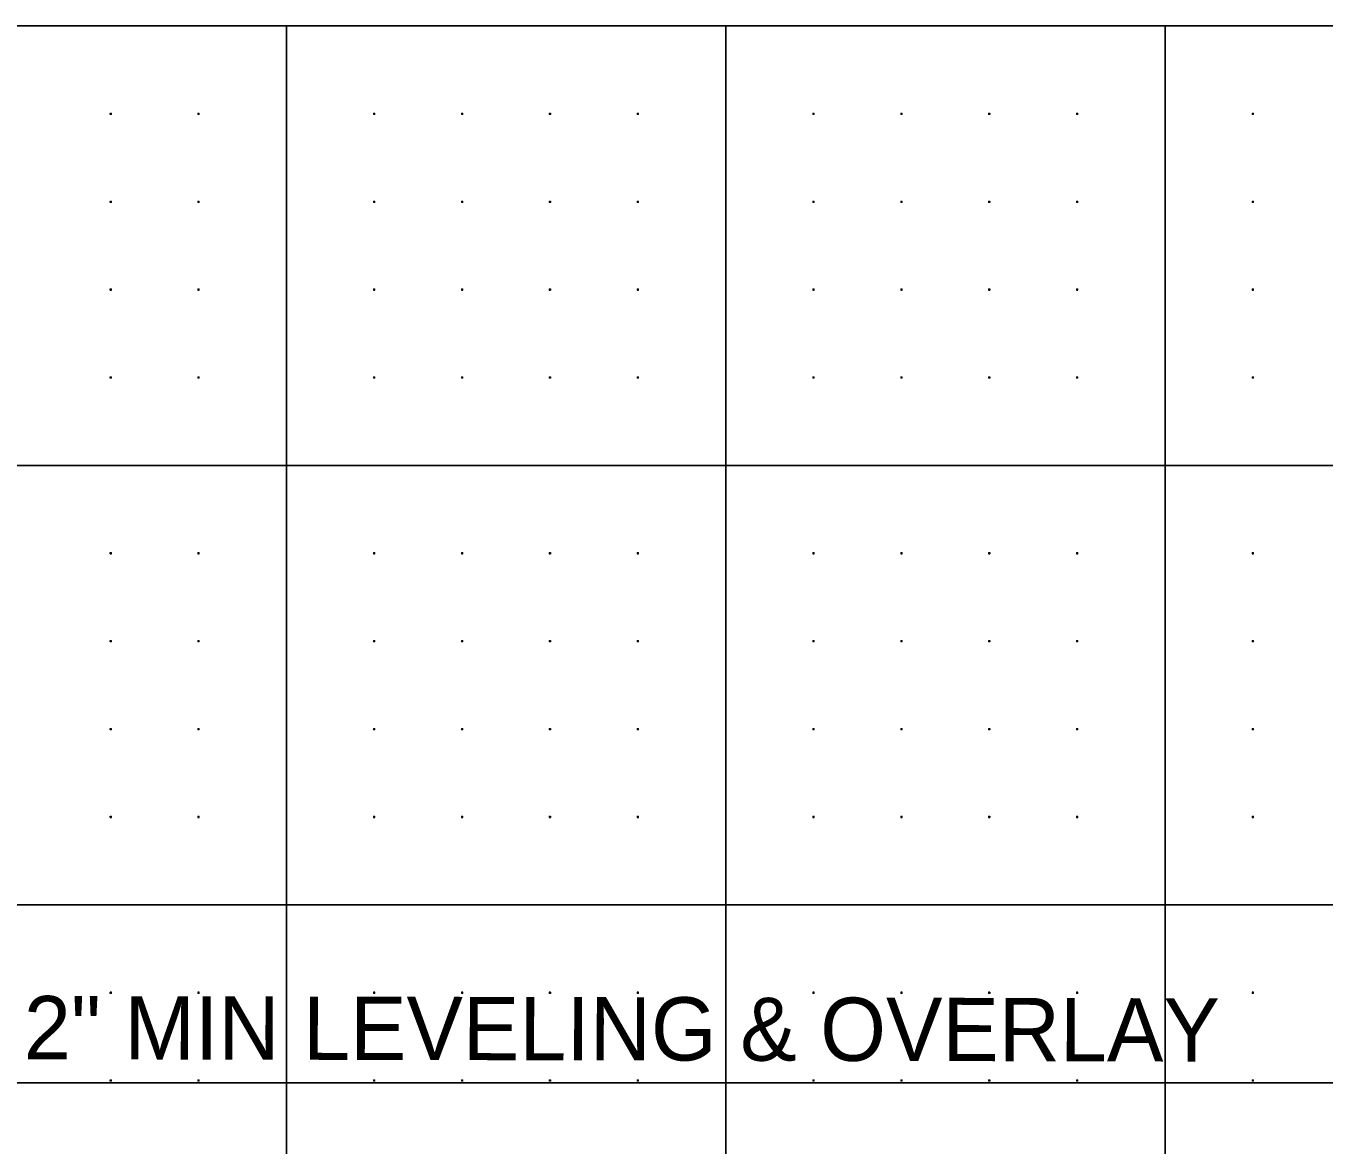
# Model space of a CAD drawing. Extents: x 471 to 2121, y 140 to 650.
# Drawn here: x 1206.4 to 1354.2, y 522.7 to 650 of the extents above; entities that cross this region are included whole.
import ezdxf

# ---------------------------------------------------------------- set-up
doc = ezdxf.new("R2010")
doc.units = 0
doc.layers.add('DSN_DRFT_Border Grid', color=7, linetype='Continuous')
doc.layers.add('Transition Dimensions', color=7, linetype='Continuous')

msp = doc.modelspace()

# ---------------------------------------------------------------- linework, layer by layer
at = {"layer": 'DSN_DRFT_Border Grid'}
for p, q in [((521.06, 650), (2071.06, 650)), ((521.06, 650), (2071.06, 650)), ((1236.06, 150), (1236.06, 650)), ((1236.06, 150), (1236.06, 650)), ((1286.06, 150), (1286.06, 650)), ((1286.06, 150), (1286.06, 650)), ((1336.06, 150), (1336.06, 650)), ((1336.06, 150), (1336.06, 650)), ((1216.18, 640), (1215.94, 640)), ((1216.18, 640), (1215.94, 640)), ((1216.06, 640.12), (1216.06, 639.88)), ((1216.06, 640.12), (1216.06, 639.88)), ((1226.18, 640), (1225.94, 640)), ((1226.18, 640), (1225.94, 640)), ((1226.06, 640.12), (1226.06, 639.88)), ((1226.06, 640.12), (1226.06, 639.88)), ((1246.18, 640), (1245.94, 640)), ((1246.18, 640), (1245.94, 640)), ((1246.06, 640.12), (1246.06, 639.88)), ((1246.06, 640.12), (1246.06, 639.88)), ((1256.18, 640), (1255.94, 640)), ((1256.18, 640), (1255.94, 640)), ((1256.06, 640.12), (1256.06, 639.88)), ((1256.06, 640.12), (1256.06, 639.88)), ((1266.18, 640), (1265.94, 640)), ((1266.18, 640), (1265.94, 640)), ((1266.06, 640.12), (1266.06, 639.88)), ((1266.06, 640.12), (1266.06, 639.88)), ((1276.18, 640), (1275.94, 640)), ((1276.18, 640), (1275.94, 640)), ((1276.06, 640.12), (1276.06, 639.88)), ((1276.06, 640.12), (1276.06, 639.88)), ((1296.18, 640), (1295.94, 640)), ((1296.18, 640), (1295.94, 640)), ((1296.06, 640.12), (1296.06, 639.88)), ((1296.06, 640.12), (1296.06, 639.88)), ((1306.18, 640), (1305.94, 640)), ((1306.18, 640), (1305.94, 640)), ((1306.06, 640.12), (1306.06, 639.88)), ((1306.06, 640.12), (1306.06, 639.88)), ((1316.18, 640), (1315.94, 640)), ((1316.18, 640), (1315.94, 640)), ((1316.06, 640.12), (1316.06, 639.88)), ((1316.06, 640.12), (1316.06, 639.88)), ((1326.18, 640), (1325.94, 640)), ((1326.18, 640), (1325.94, 640)), ((1326.06, 640.12), (1326.06, 639.88)), ((1326.06, 640.12), (1326.06, 639.88)), ((1346.18, 640), (1345.94, 640)), ((1346.18, 640), (1345.94, 640)), ((1346.06, 640.12), (1346.06, 639.88)), ((1346.06, 640.12), (1346.06, 639.88)), ((1216.18, 630), (1215.94, 630)), ((1216.18, 630), (1215.94, 630)), ((1216.06, 630.12), (1216.06, 629.88)), ((1216.06, 630.12), (1216.06, 629.88)), ((1226.18, 630), (1225.94, 630)), ((1226.18, 630), (1225.94, 630)), ((1226.06, 630.12), (1226.06, 629.88)), ((1226.06, 630.12), (1226.06, 629.88)), ((1246.18, 630), (1245.94, 630)), ((1246.18, 630), (1245.94, 630)), ((1246.06, 630.12), (1246.06, 629.88)), ((1246.06, 630.12), (1246.06, 629.88)), ((1256.18, 630), (1255.94, 630)), ((1256.18, 630), (1255.94, 630)), ((1256.06, 630.12), (1256.06, 629.88)), ((1256.06, 630.12), (1256.06, 629.88)), ((1266.18, 630), (1265.94, 630)), ((1266.18, 630), (1265.94, 630)), ((1266.06, 630.12), (1266.06, 629.88)), ((1266.06, 630.12), (1266.06, 629.88)), ((1276.18, 630), (1275.94, 630)), ((1276.18, 630), (1275.94, 630)), ((1276.06, 630.12), (1276.06, 629.88)), ((1276.06, 630.12), (1276.06, 629.88)), ((1296.18, 630), (1295.94, 630)), ((1296.18, 630), (1295.94, 630)), ((1296.06, 630.12), (1296.06, 629.88)), ((1296.06, 630.12), (1296.06, 629.88)), ((1306.18, 630), (1305.94, 630)), ((1306.18, 630), (1305.94, 630)), ((1306.06, 630.12), (1306.06, 629.88)), ((1306.06, 630.12), (1306.06, 629.88)), ((1316.18, 630), (1315.94, 630)), ((1316.18, 630), (1315.94, 630)), ((1316.06, 630.12), (1316.06, 629.88)), ((1316.06, 630.12), (1316.06, 629.88)), ((1326.18, 630), (1325.94, 630)), ((1326.18, 630), (1325.94, 630)), ((1326.06, 630.12), (1326.06, 629.88)), ((1326.06, 630.12), (1326.06, 629.88)), ((1346.18, 630), (1345.94, 630)), ((1346.18, 630), (1345.94, 630)), ((1346.06, 630.12), (1346.06, 629.88)), ((1346.06, 630.12), (1346.06, 629.88)), ((1216.18, 620), (1215.94, 620)), ((1216.18, 620), (1215.94, 620)), ((1216.06, 620.12), (1216.06, 619.88)), ((1216.06, 620.12), (1216.06, 619.88)), ((1226.18, 620), (1225.94, 620)), ((1226.18, 620), (1225.94, 620)), ((1226.06, 620.12), (1226.06, 619.88)), ((1226.06, 620.12), (1226.06, 619.88)), ((1246.18, 620), (1245.94, 620)), ((1246.18, 620), (1245.94, 620)), ((1246.06, 620.12), (1246.06, 619.88)), ((1246.06, 620.12), (1246.06, 619.88)), ((1256.18, 620), (1255.94, 620)), ((1256.18, 620), (1255.94, 620)), ((1256.06, 620.12), (1256.06, 619.88)), ((1256.06, 620.12), (1256.06, 619.88)), ((1266.18, 620), (1265.94, 620)), ((1266.18, 620), (1265.94, 620)), ((1266.06, 620.12), (1266.06, 619.88)), ((1266.06, 620.12), (1266.06, 619.88)), ((1276.18, 620), (1275.94, 620)), ((1276.18, 620), (1275.94, 620)), ((1276.06, 620.12), (1276.06, 619.88)), ((1276.06, 620.12), (1276.06, 619.88)), ((1296.18, 620), (1295.94, 620)), ((1296.18, 620), (1295.94, 620)), ((1296.06, 620.12), (1296.06, 619.88)), ((1296.06, 620.12), (1296.06, 619.88)), ((1306.18, 620), (1305.94, 620)), ((1306.18, 620), (1305.94, 620)), ((1306.06, 620.12), (1306.06, 619.88)), ((1306.06, 620.12), (1306.06, 619.88)), ((1316.18, 620), (1315.94, 620)), ((1316.18, 620), (1315.94, 620)), ((1316.06, 620.12), (1316.06, 619.88)), ((1316.06, 620.12), (1316.06, 619.88)), ((1326.18, 620), (1325.94, 620)), ((1326.18, 620), (1325.94, 620)), ((1326.06, 620.12), (1326.06, 619.88)), ((1326.06, 620.12), (1326.06, 619.88)), ((1346.18, 620), (1345.94, 620)), ((1346.18, 620), (1345.94, 620)), ((1346.06, 620.12), (1346.06, 619.88)), ((1346.06, 620.12), (1346.06, 619.88)), ((1216.18, 610), (1215.94, 610)), ((1216.18, 610), (1215.94, 610)), ((1216.06, 610.12), (1216.06, 609.88)), ((1216.06, 610.12), (1216.06, 609.88)), ((1226.18, 610), (1225.94, 610)), ((1226.18, 610), (1225.94, 610)), ((1226.06, 610.12), (1226.06, 609.88)), ((1226.06, 610.12), (1226.06, 609.88)), ((1246.18, 610), (1245.94, 610)), ((1246.18, 610), (1245.94, 610)), ((1246.06, 610.12), (1246.06, 609.88)), ((1246.06, 610.12), (1246.06, 609.88)), ((1256.18, 610), (1255.94, 610)), ((1256.18, 610), (1255.94, 610)), ((1256.06, 610.12), (1256.06, 609.88)), ((1256.06, 610.12), (1256.06, 609.88)), ((1266.18, 610), (1265.94, 610)), ((1266.18, 610), (1265.94, 610)), ((1266.06, 610.12), (1266.06, 609.88)), ((1266.06, 610.12), (1266.06, 609.88)), ((1276.18, 610), (1275.94, 610)), ((1276.18, 610), (1275.94, 610)), ((1276.06, 610.12), (1276.06, 609.88)), ((1276.06, 610.12), (1276.06, 609.88)), ((1296.18, 610), (1295.94, 610)), ((1296.18, 610), (1295.94, 610)), ((1296.06, 610.12), (1296.06, 609.88)), ((1296.06, 610.12), (1296.06, 609.88)), ((1306.18, 610), (1305.94, 610)), ((1306.18, 610), (1305.94, 610)), ((1306.06, 610.12), (1306.06, 609.88)), ((1306.06, 610.12), (1306.06, 609.88)), ((1316.18, 610), (1315.94, 610)), ((1316.18, 610), (1315.94, 610)), ((1316.06, 610.12), (1316.06, 609.88)), ((1316.06, 610.12), (1316.06, 609.88)), ((1326.18, 610), (1325.94, 610)), ((1326.18, 610), (1325.94, 610)), ((1326.06, 610.12), (1326.06, 609.88)), ((1326.06, 610.12), (1326.06, 609.88)), ((1346.18, 610), (1345.94, 610)), ((1346.18, 610), (1345.94, 610)), ((1346.06, 610.12), (1346.06, 609.88)), ((1346.06, 610.12), (1346.06, 609.88)), ((521.06, 600), (2071.06, 600)), ((521.06, 600), (2071.06, 600)), ((1216.18, 590), (1215.94, 590)), ((1216.18, 590), (1215.94, 590)), ((1216.06, 590.12), (1216.06, 589.88)), ((1216.06, 590.12), (1216.06, 589.88)), ((1226.18, 590), (1225.94, 590)), ((1226.18, 590), (1225.94, 590)), ((1226.06, 590.12), (1226.06, 589.88)), ((1226.06, 590.12), (1226.06, 589.88)), ((1246.18, 590), (1245.94, 590)), ((1246.18, 590), (1245.94, 590)), ((1246.06, 590.12), (1246.06, 589.88)), ((1246.06, 590.12), (1246.06, 589.88)), ((1256.18, 590), (1255.94, 590)), ((1256.18, 590), (1255.94, 590)), ((1256.06, 590.12), (1256.06, 589.88)), ((1256.06, 590.12), (1256.06, 589.88)), ((1266.18, 590), (1265.94, 590)), ((1266.18, 590), (1265.94, 590)), ((1266.06, 590.12), (1266.06, 589.88)), ((1266.06, 590.12), (1266.06, 589.88)), ((1276.18, 590), (1275.94, 590)), ((1276.18, 590), (1275.94, 590)), ((1276.06, 590.12), (1276.06, 589.88)), ((1276.06, 590.12), (1276.06, 589.88)), ((1296.18, 590), (1295.94, 590)), ((1296.18, 590), (1295.94, 590)), ((1296.06, 590.12), (1296.06, 589.88)), ((1296.06, 590.12), (1296.06, 589.88)), ((1306.18, 590), (1305.94, 590)), ((1306.18, 590), (1305.94, 590)), ((1306.06, 590.12), (1306.06, 589.88)), ((1306.06, 590.12), (1306.06, 589.88)), ((1316.18, 590), (1315.94, 590)), ((1316.18, 590), (1315.94, 590)), ((1316.06, 590.12), (1316.06, 589.88)), ((1316.06, 590.12), (1316.06, 589.88)), ((1326.18, 590), (1325.94, 590)), ((1326.18, 590), (1325.94, 590)), ((1326.06, 590.12), (1326.06, 589.88)), ((1326.06, 590.12), (1326.06, 589.88)), ((1346.18, 590), (1345.94, 590)), ((1346.18, 590), (1345.94, 590)), ((1346.06, 590.12), (1346.06, 589.88)), ((1346.06, 590.12), (1346.06, 589.88)), ((1216.18, 580), (1215.94, 580)), ((1216.18, 580), (1215.94, 580)), ((1216.06, 580.12), (1216.06, 579.88)), ((1216.06, 580.12), (1216.06, 579.88)), ((1226.18, 580), (1225.94, 580)), ((1226.18, 580), (1225.94, 580)), ((1226.06, 580.12), (1226.06, 579.88)), ((1226.06, 580.12), (1226.06, 579.88)), ((1246.18, 580), (1245.94, 580)), ((1246.18, 580), (1245.94, 580)), ((1246.06, 580.12), (1246.06, 579.88)), ((1246.06, 580.12), (1246.06, 579.88)), ((1256.18, 580), (1255.94, 580)), ((1256.18, 580), (1255.94, 580)), ((1256.06, 580.12), (1256.06, 579.88)), ((1256.06, 580.12), (1256.06, 579.88)), ((1266.18, 580), (1265.94, 580)), ((1266.18, 580), (1265.94, 580)), ((1266.06, 580.12), (1266.06, 579.88)), ((1266.06, 580.12), (1266.06, 579.88)), ((1276.18, 580), (1275.94, 580)), ((1276.18, 580), (1275.94, 580)), ((1276.06, 580.12), (1276.06, 579.88)), ((1276.06, 580.12), (1276.06, 579.88)), ((1296.18, 580), (1295.94, 580)), ((1296.18, 580), (1295.94, 580)), ((1296.06, 580.12), (1296.06, 579.88)), ((1296.06, 580.12), (1296.06, 579.88)), ((1306.18, 580), (1305.94, 580)), ((1306.18, 580), (1305.94, 580)), ((1306.06, 580.12), (1306.06, 579.88)), ((1306.06, 580.12), (1306.06, 579.88)), ((1316.18, 580), (1315.94, 580)), ((1316.18, 580), (1315.94, 580)), ((1316.06, 580.12), (1316.06, 579.88)), ((1316.06, 580.12), (1316.06, 579.88)), ((1326.18, 580), (1325.94, 580)), ((1326.18, 580), (1325.94, 580)), ((1326.06, 580.12), (1326.06, 579.88)), ((1326.06, 580.12), (1326.06, 579.88)), ((1346.18, 580), (1345.94, 580)), ((1346.18, 580), (1345.94, 580)), ((1346.06, 580.12), (1346.06, 579.88)), ((1346.06, 580.12), (1346.06, 579.88)), ((1216.18, 570), (1215.94, 570)), ((1216.18, 570), (1215.94, 570)), ((1216.06, 570.12), (1216.06, 569.88)), ((1216.06, 570.12), (1216.06, 569.88)), ((1226.18, 570), (1225.94, 570)), ((1226.18, 570), (1225.94, 570)), ((1226.06, 570.12), (1226.06, 569.88)), ((1226.06, 570.12), (1226.06, 569.88)), ((1246.18, 570), (1245.94, 570)), ((1246.18, 570), (1245.94, 570)), ((1246.06, 570.12), (1246.06, 569.88)), ((1246.06, 570.12), (1246.06, 569.88)), ((1256.18, 570), (1255.94, 570)), ((1256.18, 570), (1255.94, 570)), ((1256.06, 570.12), (1256.06, 569.88)), ((1256.06, 570.12), (1256.06, 569.88)), ((1266.18, 570), (1265.94, 570)), ((1266.18, 570), (1265.94, 570)), ((1266.06, 570.12), (1266.06, 569.88)), ((1266.06, 570.12), (1266.06, 569.88)), ((1276.18, 570), (1275.94, 570)), ((1276.18, 570), (1275.94, 570)), ((1276.06, 570.12), (1276.06, 569.88)), ((1276.06, 570.12), (1276.06, 569.88)), ((1296.18, 570), (1295.94, 570)), ((1296.18, 570), (1295.94, 570)), ((1296.06, 570.12), (1296.06, 569.88)), ((1296.06, 570.12), (1296.06, 569.88)), ((1306.18, 570), (1305.94, 570)), ((1306.18, 570), (1305.94, 570)), ((1306.06, 570.12), (1306.06, 569.88)), ((1306.06, 570.12), (1306.06, 569.88)), ((1316.18, 570), (1315.94, 570)), ((1316.18, 570), (1315.94, 570)), ((1316.06, 570.12), (1316.06, 569.88)), ((1316.06, 570.12), (1316.06, 569.88)), ((1326.18, 570), (1325.94, 570)), ((1326.18, 570), (1325.94, 570)), ((1326.06, 570.12), (1326.06, 569.88)), ((1326.06, 570.12), (1326.06, 569.88)), ((1346.18, 570), (1345.94, 570)), ((1346.18, 570), (1345.94, 570)), ((1346.06, 570.12), (1346.06, 569.88)), ((1346.06, 570.12), (1346.06, 569.88)), ((1216.18, 560), (1215.94, 560)), ((1216.18, 560), (1215.94, 560)), ((1216.06, 560.12), (1216.06, 559.88)), ((1216.06, 560.12), (1216.06, 559.88)), ((1226.18, 560), (1225.94, 560)), ((1226.18, 560), (1225.94, 560)), ((1226.06, 560.12), (1226.06, 559.88)), ((1226.06, 560.12), (1226.06, 559.88)), ((1246.18, 560), (1245.94, 560)), ((1246.18, 560), (1245.94, 560)), ((1246.06, 560.12), (1246.06, 559.88)), ((1246.06, 560.12), (1246.06, 559.88)), ((1256.18, 560), (1255.94, 560)), ((1256.18, 560), (1255.94, 560)), ((1256.06, 560.12), (1256.06, 559.88)), ((1256.06, 560.12), (1256.06, 559.88)), ((1266.18, 560), (1265.94, 560)), ((1266.18, 560), (1265.94, 560)), ((1266.06, 560.12), (1266.06, 559.88)), ((1266.06, 560.12), (1266.06, 559.88)), ((1276.18, 560), (1275.94, 560)), ((1276.18, 560), (1275.94, 560)), ((1276.06, 560.12), (1276.06, 559.88)), ((1276.06, 560.12), (1276.06, 559.88)), ((1296.18, 560), (1295.94, 560)), ((1296.18, 560), (1295.94, 560)), ((1296.06, 560.12), (1296.06, 559.88)), ((1296.06, 560.12), (1296.06, 559.88)), ((1306.18, 560), (1305.94, 560)), ((1306.18, 560), (1305.94, 560)), ((1306.06, 560.12), (1306.06, 559.88)), ((1306.06, 560.12), (1306.06, 559.88)), ((1316.18, 560), (1315.94, 560)), ((1316.18, 560), (1315.94, 560)), ((1316.06, 560.12), (1316.06, 559.88)), ((1316.06, 560.12), (1316.06, 559.88)), ((1326.18, 560), (1325.94, 560)), ((1326.18, 560), (1325.94, 560)), ((1326.06, 560.12), (1326.06, 559.88)), ((1326.06, 560.12), (1326.06, 559.88)), ((1346.18, 560), (1345.94, 560)), ((1346.18, 560), (1345.94, 560)), ((1346.06, 560.12), (1346.06, 559.88)), ((1346.06, 560.12), (1346.06, 559.88)), ((521.06, 550), (2071.06, 550)), ((521.06, 550), (2071.06, 550)), ((1216.18, 540), (1215.94, 540)), ((1216.18, 540), (1215.94, 540)), ((1216.06, 540.12), (1216.06, 539.88)), ((1216.06, 540.12), (1216.06, 539.88)), ((1226.18, 540), (1225.94, 540)), ((1226.18, 540), (1225.94, 540)), ((1226.06, 540.12), (1226.06, 539.88)), ((1226.06, 540.12), (1226.06, 539.88)), ((1246.18, 540), (1245.94, 540)), ((1246.18, 540), (1245.94, 540)), ((1246.06, 540.12), (1246.06, 539.88)), ((1246.06, 540.12), (1246.06, 539.88)), ((1256.18, 540), (1255.94, 540)), ((1256.18, 540), (1255.94, 540)), ((1256.06, 540.12), (1256.06, 539.88)), ((1256.06, 540.12), (1256.06, 539.88)), ((1266.18, 540), (1265.94, 540)), ((1266.18, 540), (1265.94, 540)), ((1266.06, 540.12), (1266.06, 539.88)), ((1266.06, 540.12), (1266.06, 539.88)), ((1276.18, 540), (1275.94, 540)), ((1276.18, 540), (1275.94, 540)), ((1276.06, 540.12), (1276.06, 539.88)), ((1276.06, 540.12), (1276.06, 539.88)), ((1296.18, 540), (1295.94, 540)), ((1296.18, 540), (1295.94, 540)), ((1296.06, 540.12), (1296.06, 539.88)), ((1296.06, 540.12), (1296.06, 539.88)), ((1306.18, 540), (1305.94, 540)), ((1306.18, 540), (1305.94, 540)), ((1306.06, 540.12), (1306.06, 539.88)), ((1306.06, 540.12), (1306.06, 539.88)), ((1316.18, 540), (1315.94, 540)), ((1316.18, 540), (1315.94, 540)), ((1316.06, 540.12), (1316.06, 539.88)), ((1316.06, 540.12), (1316.06, 539.88)), ((1326.18, 540), (1325.94, 540)), ((1326.18, 540), (1325.94, 540)), ((1326.06, 540.12), (1326.06, 539.88)), ((1326.06, 540.12), (1326.06, 539.88)), ((1346.18, 540), (1345.94, 540)), ((1346.18, 540), (1345.94, 540)), ((1346.06, 540.12), (1346.06, 539.88)), ((1346.06, 540.12), (1346.06, 539.88)), ((1216.18, 530), (1215.94, 530)), ((1216.18, 530), (1215.94, 530)), ((1216.06, 530.12), (1216.06, 529.88)), ((1216.06, 530.12), (1216.06, 529.88)), ((1226.18, 530), (1225.94, 530)), ((1226.18, 530), (1225.94, 530)), ((1226.06, 530.12), (1226.06, 529.88)), ((1226.06, 530.12), (1226.06, 529.88)), ((1246.18, 530), (1245.94, 530)), ((1246.18, 530), (1245.94, 530)), ((1246.06, 530.12), (1246.06, 529.88)), ((1246.06, 530.12), (1246.06, 529.88)), ((1256.18, 530), (1255.94, 530)), ((1256.18, 530), (1255.94, 530)), ((1256.06, 530.12), (1256.06, 529.88)), ((1256.06, 530.12), (1256.06, 529.88)), ((1266.18, 530), (1265.94, 530)), ((1266.18, 530), (1265.94, 530)), ((1266.06, 530.12), (1266.06, 529.88)), ((1266.06, 530.12), (1266.06, 529.88)), ((1276.18, 530), (1275.94, 530)), ((1276.18, 530), (1275.94, 530)), ((1276.06, 530.12), (1276.06, 529.88)), ((1276.06, 530.12), (1276.06, 529.88)), ((1296.18, 530), (1295.94, 530)), ((1296.18, 530), (1295.94, 530)), ((1296.06, 530.12), (1296.06, 529.88)), ((1296.06, 530.12), (1296.06, 529.88)), ((1306.18, 530), (1305.94, 530)), ((1306.18, 530), (1305.94, 530)), ((1306.06, 530.12), (1306.06, 529.88)), ((1306.06, 530.12), (1306.06, 529.88)), ((1316.18, 530), (1315.94, 530)), ((1316.18, 530), (1315.94, 530)), ((1316.06, 530.12), (1316.06, 529.88)), ((1316.06, 530.12), (1316.06, 529.88)), ((1326.18, 530), (1325.94, 530)), ((1326.18, 530), (1325.94, 530)), ((1326.06, 530.12), (1326.06, 529.88)), ((1326.06, 530.12), (1326.06, 529.88)), ((1346.18, 530), (1345.94, 530)), ((1346.18, 530), (1345.94, 530)), ((1346.06, 530.12), (1346.06, 529.88)), ((1346.06, 530.12), (1346.06, 529.88))]:
    msp.add_line(p, q, dxfattribs=at)
at = {"layer": 'Transition Dimensions'}
msp.add_line((536.06, 529.75), (1956.06, 529.75), dxfattribs=at)

# ---------------------------------------------------------------- texts
msp.add_text('2" MIN LEVELING & OVERLAY', height=7.2, rotation=359.8866, dxfattribs=at).set_placement((1206.17, 532.43))

doc.saveas('drawing.dxf')
